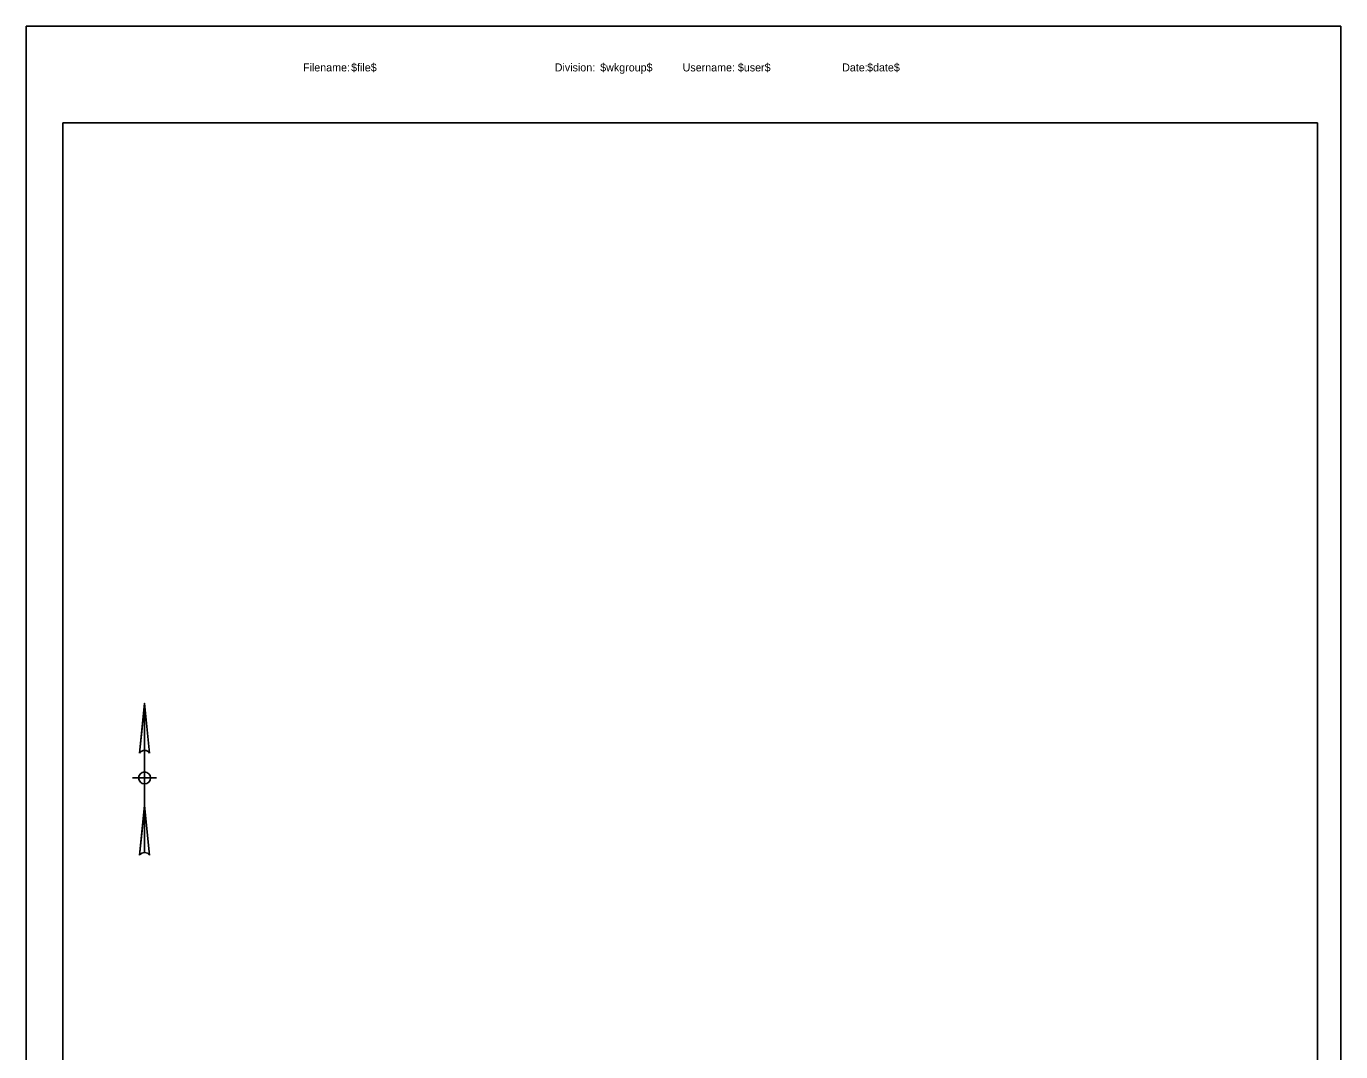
# Model space of a CAD drawing. Extents: x 1744367 to 1744917, y 463404 to 464262.
# Drawn here: x 1744367 to 1744917, y 463833 to 464262 of the extents above; entities that cross this region are included whole.
import ezdxf

# ---------------------------------------------------------------- set-up
doc = ezdxf.new("R2010")
doc.units = 0
for name, color, linetype in [('D_Roadway_SubGrade', 7, 'Continuous'), ('D_Utilities_Pole_Joint', 7, 'Continuous'), ('PLOT BOUNDARY', 7, 'Continuous'), ('Route Labels', 7, 'Continuous')]:
    doc.layers.add(name, color=color, linetype=linetype)

msp = doc.modelspace()

# ---------------------------------------------------------------- linework, layer by layer
at = {"layer": 'D_Roadway_SubGrade'}
msp.add_lwpolyline([(1744907.15, 464221.98), (1744907.15, 463471.98), (1744382.15, 463471.98), (1744382.15, 464221.98)], close=True, dxfattribs=at)
at = {"layer": 'D_Utilities_Pole_Joint'}
for p, q in [((1744414.26, 463958.34), (1744416.35, 463979.17)), ((1744416.35, 463979.17), (1744416.35, 463916.67)), ((1744416.35, 463979.17), (1744418.43, 463958.34)), ((1744411.35, 463947.92), (1744421.35, 463947.92)), ((1744414.26, 463915.55), (1744416.35, 463936.38)), ((1744416.35, 463936.38), (1744418.43, 463915.55))]:
    msp.add_line(p, q, dxfattribs=at)
for points in [[(1744418.43, 463958.34), (1744416.35, 463979.17), (1744415.3, 463968.75), (1744414.26, 463958.34)], [(1744418.43, 463915.55), (1744416.35, 463936.38), (1744415.3, 463925.97), (1744414.26, 463915.55)]]:
    msp.add_lwpolyline(points, dxfattribs=at)
msp.add_circle((1744416.35, 463947.92), 2.5, dxfattribs=at)
for centre in [(1744416.35, 463956.95), (1744416.35, 463956.95), (1744416.35, 463914.17), (1744416.35, 463914.17)]:
    msp.add_arc(centre, 2.5, 33.5573, 146.4427, dxfattribs=at)
at = {"layer": 'PLOT BOUNDARY'}
msp.add_lwpolyline([(1744907.15, 464221.98), (1744907.15, 463421.98), (1744382.15, 463421.98), (1744382.15, 464221.98)], close=True, dxfattribs=at)
at = {"layer": 'Route Labels'}
msp.add_lwpolyline([(1744366.86, 464262.45), (1744366.86, 463412.45), (1744916.86, 463412.45), (1744916.86, 464262.45)], close=True, dxfattribs=at)

# ---------------------------------------------------------------- texts
at = {"layer": 'PLOT BOUNDARY'}
for s, p in [('Filename:', (1744482.64, 464243.56)), ('$file$', (1744502.78, 464243.56)), ('Division:', (1744587.98, 464243.56)), ('$wkgroup$', (1744607, 464243.56)), ('Username:', (1744641.49, 464243.56)), ('$user$', (1744664.61, 464243.56)), ('Date:', (1744708.24, 464243.56)), ('$date$', (1744718.68, 464243.56))]:
    msp.add_text(s, height=3.348, rotation=360, dxfattribs=at).set_placement(p)

doc.saveas('drawing.dxf')
